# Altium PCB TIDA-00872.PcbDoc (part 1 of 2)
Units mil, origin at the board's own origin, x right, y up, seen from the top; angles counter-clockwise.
Board outline 2300 x 2250 mil, 2 copper layers (Top Layer, Bottom Layer), stack 64.8 mil thick; 81 components, 62 nets, 253 pads, 305 vias.
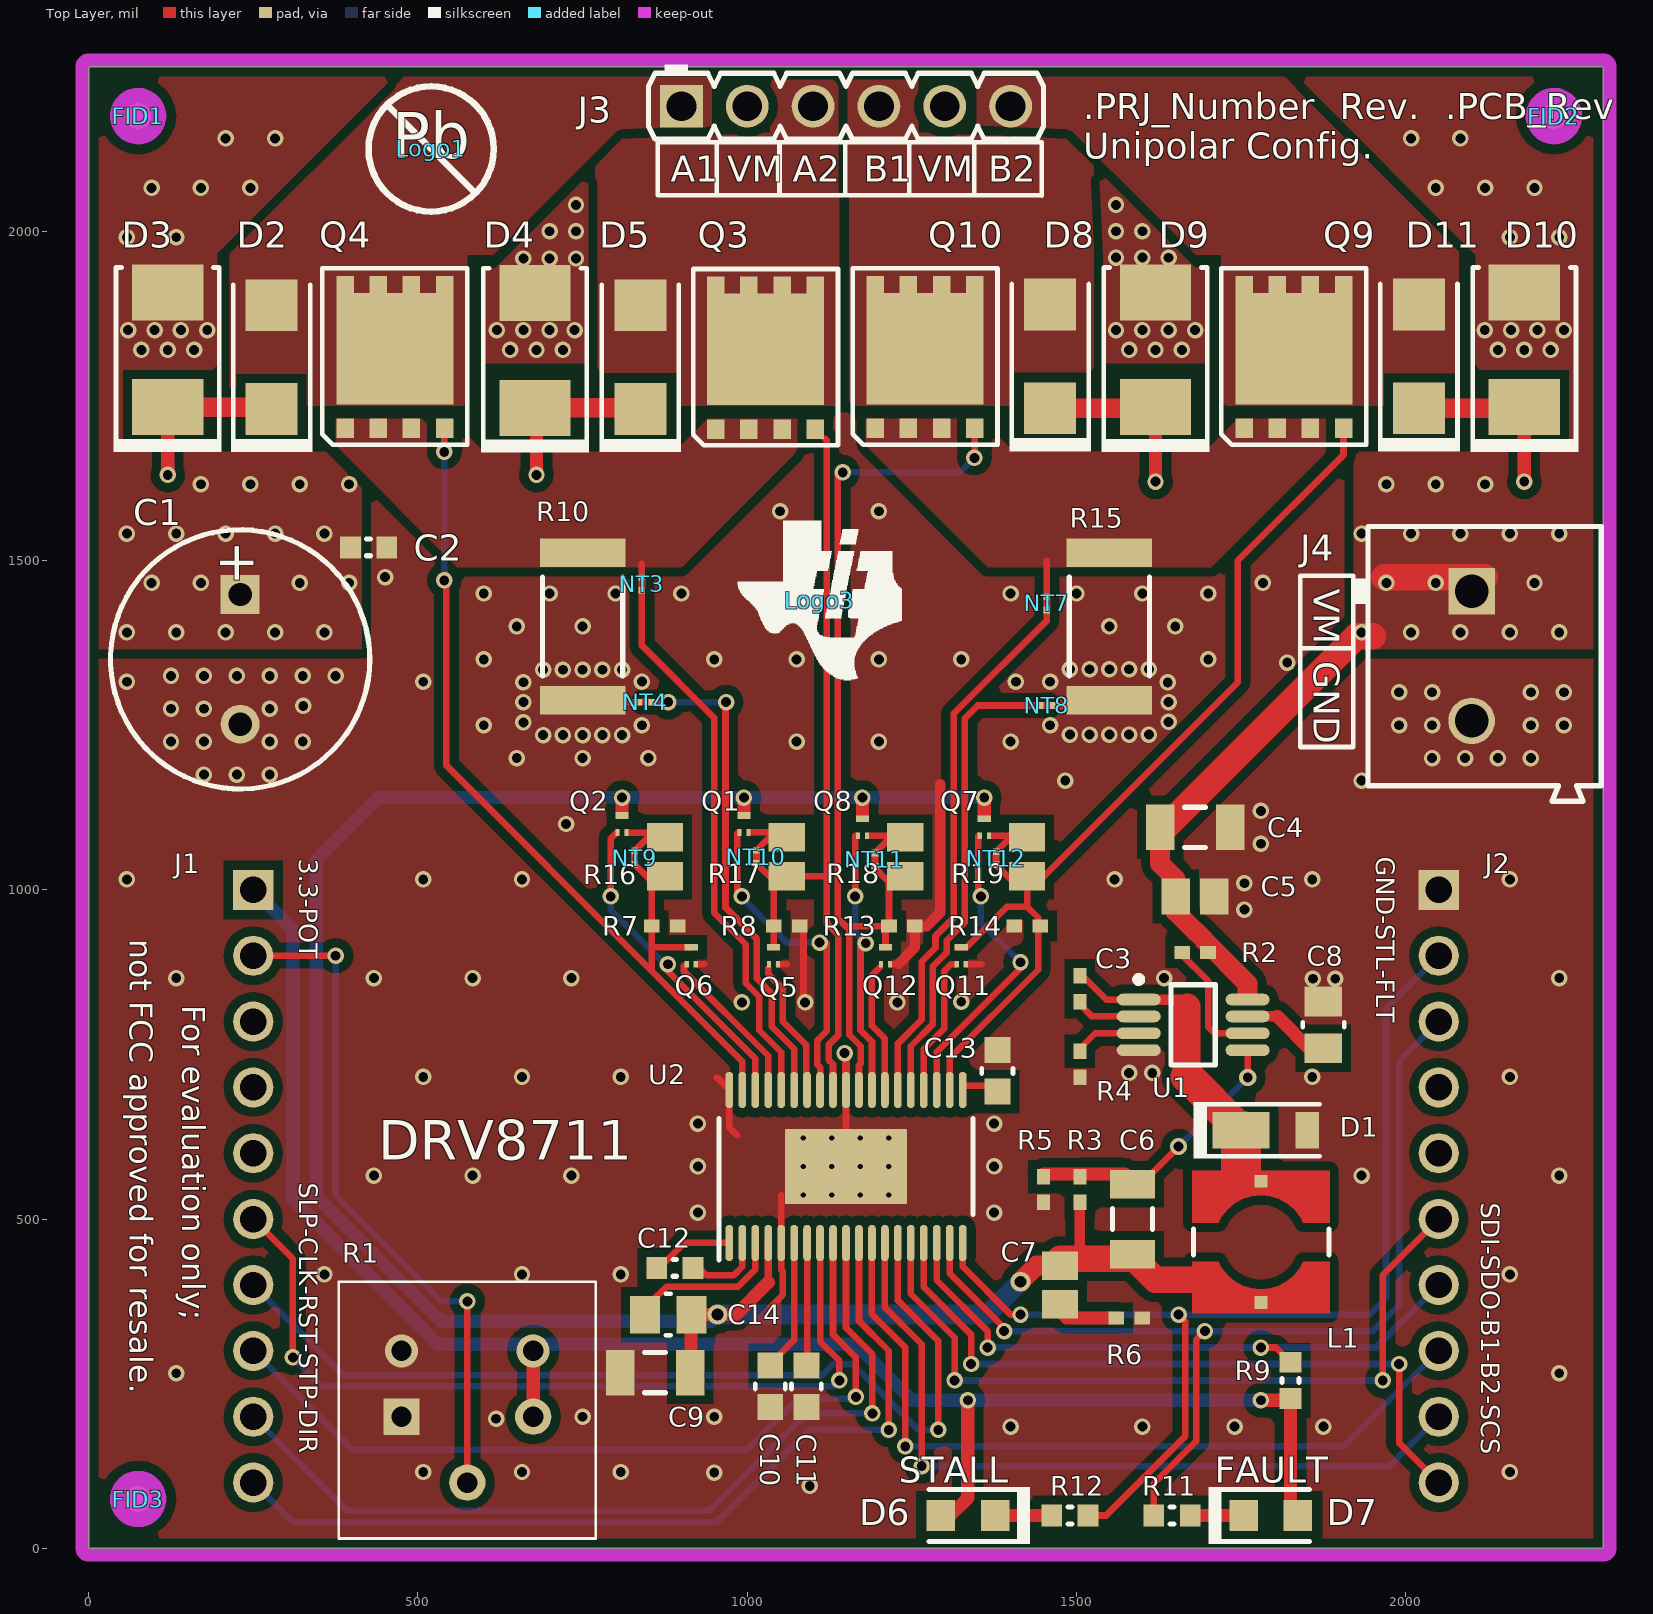
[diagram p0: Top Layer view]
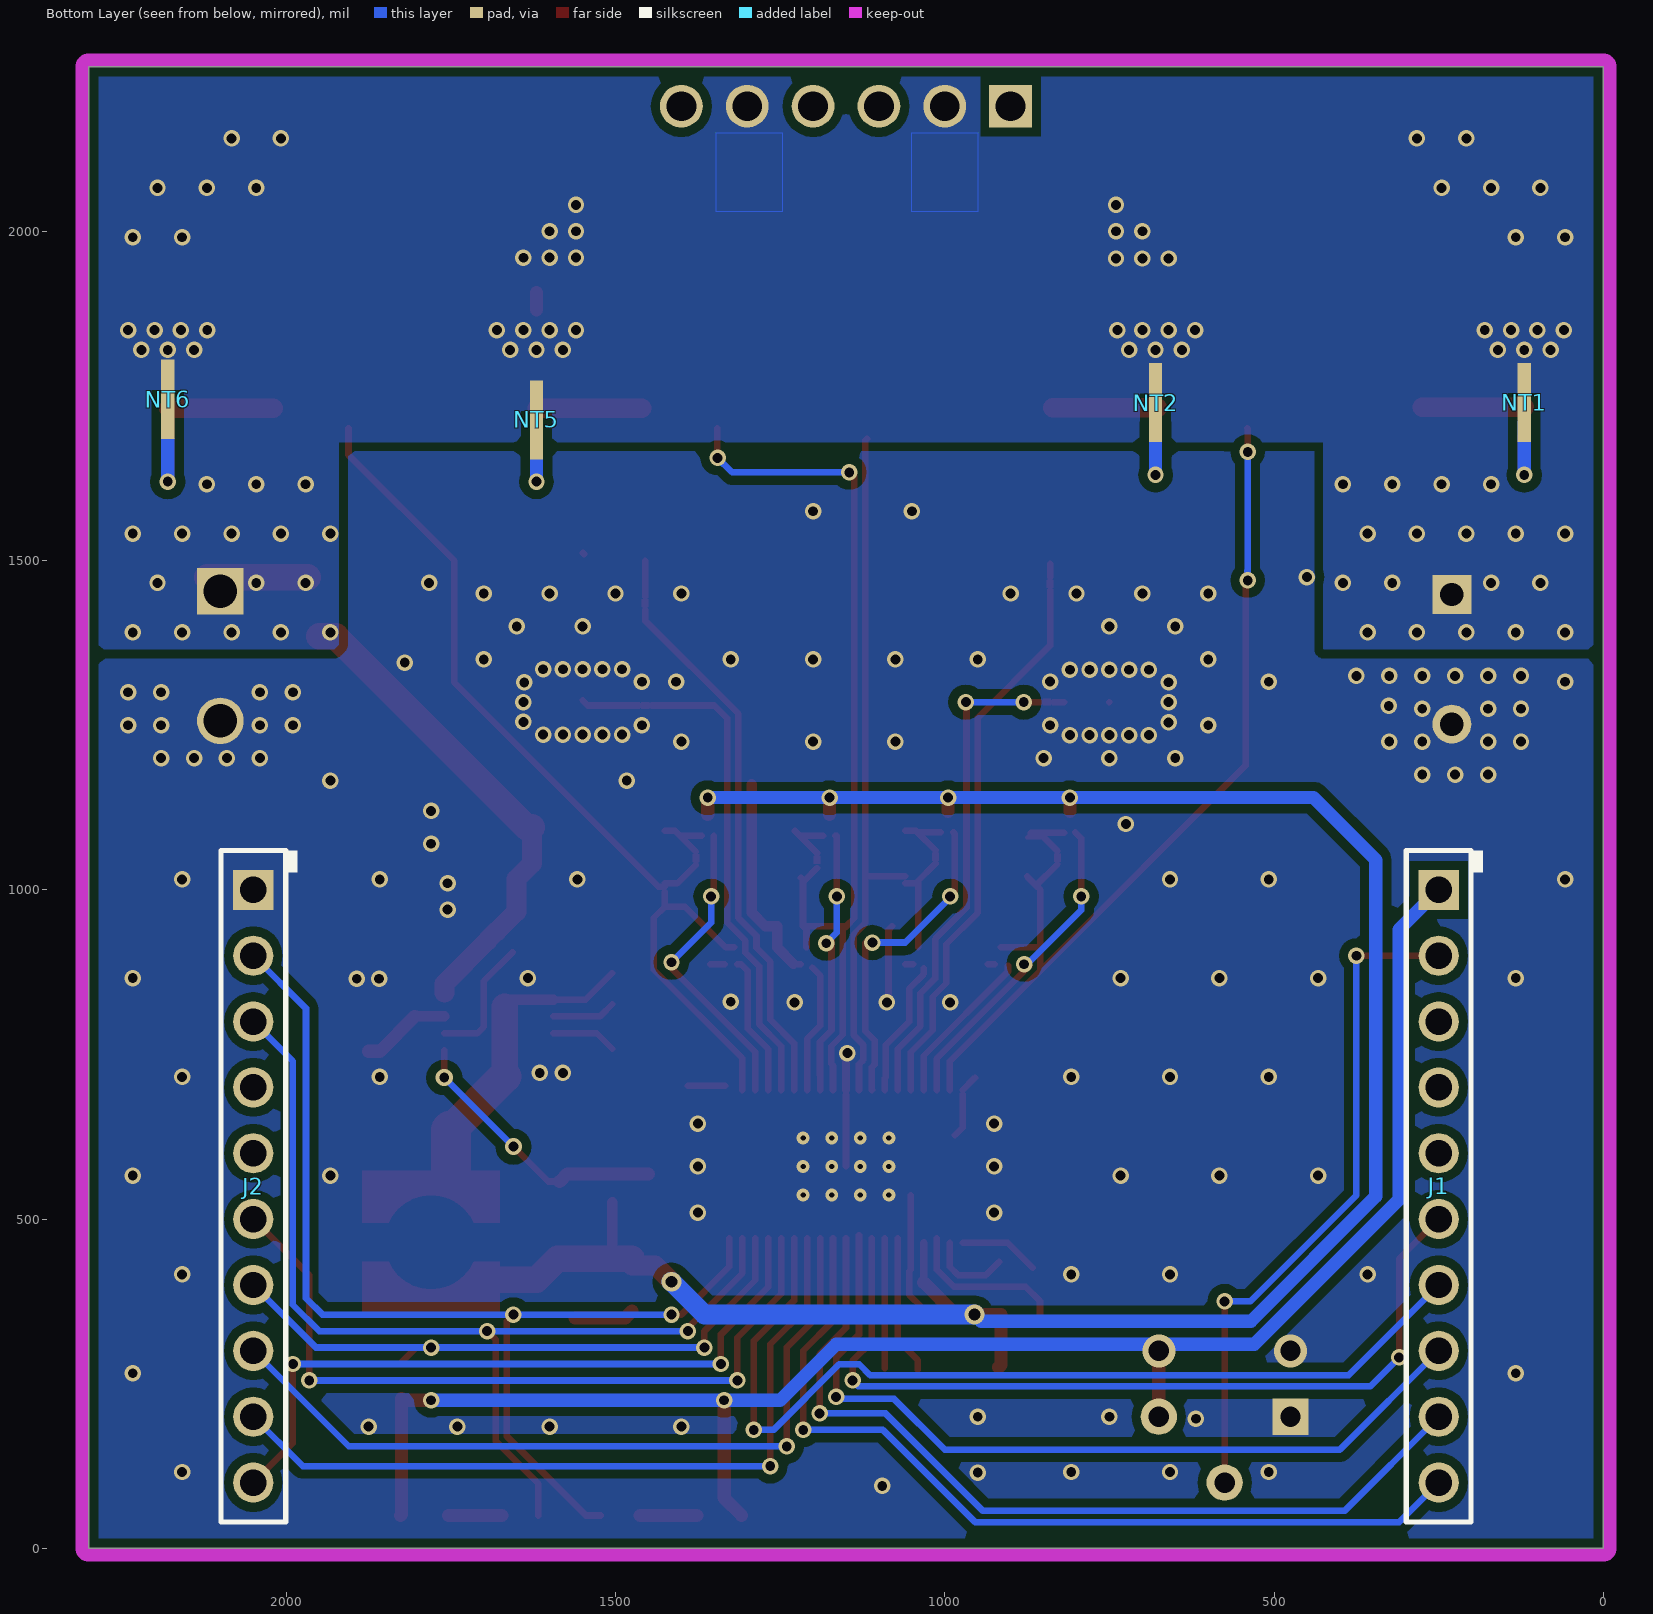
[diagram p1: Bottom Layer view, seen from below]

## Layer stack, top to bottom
Top Solder: solder mask 0.4, Solder Resist, Dk 3.5
Top Layer: signal copper 2.8
Dielectric1: core 59.2, FR-4, Dk 4.8
Bottom Layer: signal copper 2.8
Bottom Solder: solder mask 0.4, Solder Resist, Dk 3.5

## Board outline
0,0 0,2250 2300,2250 2300,0

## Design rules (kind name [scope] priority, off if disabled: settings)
AcuteAngle [All] p1: minimum=4.50000000000000E+0001 checktracksonly=FALSE
AssemblyTestPointUsage [All] p1: valid=2
Clearance Clearance_BoardEdge_MountingHoles [OnCopper and InComponentClass('Mounting Holes') vs IsKeepOut] p1: gap=15
Clearance Clearance_BoardEdge_Poly [OnCopper and InPoly vs IsKeepOut] p2: gap=15
Clearance Clearance_BoardEdge [OnCopper and Not InComponentClass('Logo') and not InComponentClass('FiducialMark') and not InRegion(1000,500,4000,800) and Not IsKeepout vs IsKeepOut] p3: gap=25
Clearance Clearance_Poly [InPolygon] p4: gap=14
Clearance [All] p5: gap=7
ComponentClearance ComponentClearance_Logo [InComponentClass(Logo)] p1: gap=10 collisioncheckmode=3 verticalgap=10 showdistances=FALSE
ComponentClearance ComponentClearance_ScrewToNut [(HasFootprint('NY PMS 440 0025 PH')) vs (HasFootprint('Keystone_1902C'))] p2: gap=5 collisioncheckmode=3 verticalgap=10 showdistances=FALSE
ComponentClearance ComponentClearance_MountingHoles [InComponentClass('Mounting Holes')] p3: gap=250 collisioncheckmode=3 verticalgap=100000 showdistances=FALSE
ComponentClearance ComponentClearance_SmallPassives [HasFootprint('0201*') or HasFootprint('0402*') or HasFootprint('0508') or HasFootprint('0603*') or HasFootprint('0612') or HasFootprint('0805*') or HasFootprint('0815*') or HasFootprint('0830*') or HasFootprint('1206*') or HasFootprint('1210*') or HasFootprint('1808*') or HasFootprint('1812*') or HasFootprint('1825*') or HasFootprint('2010*') or HasFootprint('2220*') or HasFootprint('2225*') or HasFootprint('2512*') or HasFootprint('2728*') or HasFootprint('3518*') vs HasFootprint('0201*') or HasFootprint('0402*') or HasFootprint('0508') or HasFootprint('0603*') or HasFootprint('0612') or HasFootprint('0805*') or HasFootprint('0815*') or HasFootprint('0830*') or HasFootprint('1206*') or HasFootprint('1210*') or HasFootprint('1808*') or HasFootprint('1812*') or HasFootprint('1825*') or HasFootprint('2010*') or HasFootprint('2220*') or HasFootprint('2225*') or HasFootprint('2512*') or HasFootprint('2728*') or HasFootprint('3518*')] p4: gap=10 collisioncheckmode=3 verticalgap=10 showdistances=FALSE
ComponentClearance ComponentClearance_THtoSMT [IsThruComponent vs IsSMTComponent] p5: gap=10 collisioncheckmode=3 verticalgap=100000 showdistances=FALSE
ComponentClearance ComponentClearance_THtoTH [IsThruComponent vs IsThruComponent] p6: gap=0 collisioncheckmode=3 verticalgap=0 showdistances=FALSE
ComponentClearance [All] p7: gap=10 collisioncheckmode=3 verticalgap=10 showdistances=FALSE
DiffPairsRouting [All] p1: maxlimit=100 minlimit=10 mostfreqgap=10 toplayer_minwidth=15 toplayer_maxwidth=15 toplayer_prefwidth=15 bottomlayer_minwidth=15 bottomlayer_maxwidth=15 bottomlayer_prefwidth=15 maxuncoupledlength=1000
FabricationTestPointUsage TestPointUsage [All] p1: valid=2 allowmultiple=FALSE
FabricationTestpoint Testpoint [All] p1: side=3 testpointundercomponent=TRUE minsize=40 maxsize=100 preferedsize=60 minholesize=0 maxholesize=40 preferedholesize=32 testpointgrid=1 allowsidetop=TRUE allowsidebottom=TRUE usegrid=TRUE gridtolerance=0.01
FanoutControl Fanout_LCC [IsLCC] p1: bgadir=Out bgaviamode=Centered fanoutstyle=Auto fanoutdirection=Alternating viagrid=1 // Fanout_LCC (Default Rule)
FanoutControl Fanout_BGA [IsBGA] p2: bgadir=Out bgaviamode=Centered fanoutstyle=Auto fanoutdirection=Alternating viagrid=1 // Fanout_BGA (Default Rule)
FanoutControl Fanout_Default [All] p4: bgadir=Out bgaviamode=Centered fanoutstyle=Auto fanoutdirection=Alternating viagrid=1 // Fanout_Default (Default Rule)
FanoutControl Fanout_Small [(CompPinCount < 5)] p5: bgadir=Out bgaviamode=Centered fanoutstyle=Auto fanoutdirection=OutThenIn viagrid=1 // Fanout_Small (Default Rule)
HoleSize [All] p1: absolutevalues=TRUE maxlimit=251 minlimit=7.8 maxpercent=80.000 minpercent=20.000
MinimumAnnularRing [All] p1: minimumring=5
MinimumSolderMaskSliver MinimumSolderMaskSliver_Logo [InComponentClass('Logo') vs InComponentClass('Logo')] p1: minsoldermaskwidth=0.7
MinimumSolderMaskSliver [All] p2: minsoldermaskwidth=0.4
PlaneClearance [All] p1: clearance=15
PlaneConnect [All] p1: planeconnectstyle=Direct reliefexpansion=10 reliefentries=4 reliefconductorwidth=10 reliefairgap=10
PolygonConnect PolygonConnect_1 [IsNamedPolygon('GND_TOP') or IsNamedPolygon('GND_BOT') vs Not (InComponent('U1') or InComponent('J2') or InComponent('J3') or InComponent('J5') or InComponent('C1') or InComponent('R1') or InComponent('R2') or IsStitchingVia or IsVia)] p1: connectstyle=Direct reliefconductorwidth=10 reliefentries=4 polygonreliefangle="90 Angle" airgapwidth=10
PolygonConnect [All] p2: connectstyle=Direct reliefconductorwidth=10 reliefentries=4 polygonreliefangle="90 Angle" airgapwidth=10
RoutingVias [All] p1: holewidth=15 width=25 viastyle="Through Hole" minholewidth=7.8 minwidth=19 maxholewidth=40 maxwidth=65
SMDToCorner [All] p1: distance=15000
SilkToSilkClearance [All] p1: silktosilkclearance=2
SilkToSolderMaskClearance SilkscreenOverComponentPads [All] p1: minsilkscreentomaskgap=1 clearancetoexposedcopper=FALSE
SolderMaskExpansion [All] p1: expansion=3
UnpouredPolygon [All] p1: allowunpoured=FALSE
Width [All] p1: maxlimit=100 minlimit=6 preferedwidth=10 checkconnectedcopper=TRUE
14 further rules are at their usual default settings.

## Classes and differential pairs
component class Header: J3
component class TIDA-00872_Unipolar: C1 C2 C3 C4 C5 C6 C7 C8 D1 FID1 FID2 FID3 J1 J2 J3 J4 L1 Logo1 Logo2 Logo3 R1 R2 R3 R4 R5 R6 U1
component class Logo: Logo3
component class TIDA-00872_Driver_UnipolarMotor: C9 C10 C11 C12 C13 C14 D2 D3 D4 D5 D6 D7 D8 D9 D10 D11 NT1 NT2 NT3 NT4 NT5 NT6 NT7 NT8 NT9 NT10 NT11 NT12 Q1 Q2 Q3 Q4 Q5 Q6 Q7 Q8 Q9 Q10 Q11 Q12 R7 R8 R9 R10 R11 R12 R13 R14 R15 R16 R17 R18 R19 U2
component class FiducialMark: FID1 FID2 FID3

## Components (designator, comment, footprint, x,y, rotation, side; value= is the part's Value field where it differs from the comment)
C1 "ECA-2AM101" CAPPR5-10X20 230,1350 r270 top
C2 "C1608X7R2A103K" 0603L 425,1520 r0 top
C3 "885012205031" 0402L 1505,850 r90 top
C4 "C3216X7R2A105M160AA" 1206L 1680,1095 r0 top
C5 "C2012X7R2A104K125AA" 0805L 1680,990 r0 top
C6 "C1206C122K5RACTU" 1206L 1585,500 r90 top
C7 "885012107013" 0805_145L 1475,400 r270 top
C8 "885012207049" 0805_140 1875,795 r90 top
C9 "HMK316B7105KL-T" 1206L 860,267 r180 top
C10 "885012206071" 0603_095 1035,246 r270 top
C11 "885012206052" 0603_095 1090,246 r270 top
C12 "GRM188R72A104KA35D" 0603L 890,426 r0 top
C13 "885012206034" 0603_095 1380,725 r90 top
C14 "885012207103" 0805_140 880,355 r0 top
D1 "DFLS1100-7" powerDI123 1800,635 r0 top
D2 "RB050L-60TE25" SMA 277.8,1808.97 r90 top
D3 "SMBJ60A-13-F" SMB 120,1820 r90 top
D4 "SMBJ60A-13-F" SMB 677.8,1818.97 r90 top
D5 "RB050L-60TE25" SMA 837.79,1808.97 r90 top
D6 "150080SS75000" WL-SMCW_RED_0805 1335,50 r180 top
D7 "150080SS75000" WL-SMCW_RED_0805 1795,50 r0 top
D8 "RB050L-60TE25" SMA 1460,1810 r90 top
D9 "SMBJ60A-13-F" SMB 1620,1820 r90 top
D10 "SMBJ60A-13-F" SMB 2180,1820 r90 top
D11 "RB050L-60TE25" SMA 2020,1810 r90 top
FID1 "Fiducial" Fiducial10-20 75,2175 r0 top
FID2 "Fiducial" Fiducial10-20 2225,2175 r0 top
FID3 "Fiducial" Fiducial10-20 75,75 r0 top
J1 "61301011821" Wurth_61301011821 250,550 r270 bottom
J2 "61301011821" Wurth_61301011821 2050,550 r270 bottom
J3 "61300611121" WURTH_61300611121 1150,2190 r0 top
J4 "691 101 710 002" Wurth_691101710002 2100,1355 r270 top
L1 "744043471" WE-TPC_4828 1780,465 r270 top
Logo1 "Pb-Free Symbol" Pb-Free_Overlay_Medium 520,2125 r0 top
Logo2 "FCC disclaimer" FCC_disclaimer_stacked -280,-170 r180 top
Logo3 "Texas Instruments" TI_Symbol_Overlay_Medium 1110,1440 r0 top
NT1 "Net-Tie" Net-Tie_20milWide_60milLong 120,1740 r90 bottom net-tie
NT2 "Net-Tie" Net-Tie_20milWide_60milLong 680,1740 r270 bottom net-tie
NT3 "Net-Tie" Net-Tie_10mil 840,1465 r90 top net-tie
NT4 "Net-Tie" Net-Tie_10mil 845,1285 r180 top net-tie
NT5 "Net-Tie" Net-Tie_20milWide_60milLong 1619.99,1713.7 r90 bottom net-tie
NT6 "Net-Tie" Net-Tie_20milWide_60milLong 2180,1745 r270 bottom net-tie
NT7 "Net-Tie" Net-Tie_10mil 1455,1435 r270 top net-tie
NT8 "Net-Tie" Net-Tie_10mil 1455,1280 r180 top net-tie
NT9 "Net-Tie" Net-Tie_10mil 829,1049 r90 top net-tie
NT10 "Net-Tie" Net-Tie_10mil 1014,1050 r90 top net-tie
NT11 "Net-Tie" Net-Tie_10mil 1194,1046 r90 top net-tie
NT12 "Net-Tie" Net-Tie_10mil 1378,1048 r90 top net-tie
Q1 "CSD17483F4T" YJC0003A 995,1100 r0 top
Q2 "CSD17483F4T" YJC0003A 810,1100 r0 top
Q3 "CSD19534Q5A" TRANS_NexFET_Q5A 1027.8,1808.97 r90 top
Q4 "CSD19534Q5A" TRANS_NexFET_Q5A 465,1810 r90 top
Q5 "CSD17483F4T" YJC0003A 1040,900 r0 top
Q6 "CSD17483F4T" YJC0003A 915,900 r0 top
Q7 "CSD17483F4T" YJC0003A 1360,1095 r0 top
Q8 "CSD17483F4T" YJC0003A 1175,1095 r0 top
Q9 "CSD19534Q5A" TRANS_NexFET_Q5A 1830,1810 r90 top
Q10 "CSD19534Q5A" TRANS_NexFET_Q5A 1270,1810 r90 top
Q11 "CSD17483F4T" YJC0003A 1325,900 r0 top
Q12 "CSD17483F4T" YJC0003A 1210,900 r0 top
R1 "3386P-1-104LF" BOURNS_3386P 575,210 r0 top
R2 "CRCW0402274KFKED" 0402L 1680,905 r180 top
R3 "ERJ-2RKF2201X" 0402L 1505,545 r270 top
R4 "CRCW0402154KFKED" 0402L 1505,735 r90 top
R5 "CRCW0402576RFKED" 0402L 1450,545 r90 top
R6 "ERJ-2BQFR68X" 0402L 1580,350 r180 top
R7 "CRCW0402100KFKED" 0402L 875,945 r180 top
R8 "CRCW0402100KFKED" 0402L 1060,945 r180 top
R9 "CRCW06033K30JNEA" 0603L 1825,255 r270 top
R10 "CRA2512-FZ-R050ELF" 2512L 750,1400 r90 top
R11 "CRCW0603330RJNEA" 0603L 1645,50 r180 top
R12 "CRCW0603330RJNEA" 0603L 1490,50 r180 top
R13 "CRCW0402100KFKED" 0402L 1235,945 r180 top
R14 "CRCW0402100KFKED" 0402L 1425,945 r0 top
R15 "CRA2512-FZ-R050ELF" 2512L 1550,1400 r90 top
R16 "CRCW0805100RFKEA" 0805L 875,1050 r90 top
R17 "CRCW0805100RFKEA" 0805L 1060,1050 r90 top
R18 "CRCW0805100RFKEA" 0805L 1240,1050 r90 top
R19 "CRCW0805100RFKEA" 0805L 1425,1050 r90 top
U1 "LM5009MM/NOPB" MUA08A_N 1677.17,795 r0 top
U2 "DRV8711DCPR" DCP0038A_N 1150,580 r90 top

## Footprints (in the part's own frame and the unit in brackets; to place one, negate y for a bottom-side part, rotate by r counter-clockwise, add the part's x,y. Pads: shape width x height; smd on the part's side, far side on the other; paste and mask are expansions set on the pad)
0402L [mm] "0402 from SM-752 data"
  rect 0.6x0.5 smd: 1(-0.5,0) 2(0.5,0)
  body extent -0.55,-0.3 0.55,0.3, height 0.6
0603_095 [mm] "0603_095"
  rect 1x1 smd: 1(-0.8,0) 2(0.8,0)
  silkscreen extent -0.1,-0.58 0.1,0.58, body extent -0.87,-0.48 0.87,0.48, height 0.95
0603L [mm] "0603 from SM-752 data"
  rect 0.8x0.85 smd: 1(-0.7,0) 2(0.7,0)
  silkscreen extent -0.07,-0.33 0.07,0.33, body extent -0.87,-0.47 0.87,0.47, height 0.85
0805_140 [mm] "0805 / 1.4mm height"
  rect 1.15x1.45 smd: 1(-0.9,0) 2(0.9,0)
  silkscreen extent -0.1,-0.8 0.1,0.8, body extent -1.1,-0.72 1.1,0.72, height 1.4
0805_145L [mm] "0805 / 1.45mm height"
  rect 1.1x1.4 smd: 1(-0.75,0) 2(0.75,0)
  body extent -1.1,-0.72 1.1,0.72, height 1.45
0805L [mm] "0805 from SM-752 data"
  rect 1.1x1.4 smd: 1(-0.75,0) 2(0.75,0)
  body extent -1.1,-0.72 1.1,0.72, height 1.1
1206L [mm] "1206 from SM-752 data"
  rect 1.1x1.75 smd: 1(-1.35,0) 2(1.35,0)
  silkscreen extent -0.4,-0.77 0.4,0.77, body extent -1.7,-0.9 1.7,0.9, height 1.35
2512L [mm] "Chip Resistor, Body 6.3x3.2mm, IPC High Density"
  rect 1.1x3.3 smd: 1(-2.85,0) 2(2.85,0)
  silkscreen extent -1.9,-1.55 1.9,1.55, body extent -3.22,-1.67 3.22,1.67, height 0.71
BOURNS_3386P [mil] "BOURND"
  rect 55x55 hole 31: 1(-100,-10)
  round 55 hole 31: 2(0,-110) 3(100,-10)
  silkscreen extent -195,-195 195,195, body extent -193,-192 193,193, height 201
CAPPR5-10X20 [mm] "Capacitor, Electrolytic, Radial; Body 10 x 20 mm (Dia.xH typ); Pin Spacing 5 mm (typ)"
  rect 1.5x1.5 hole 0.9: 1(-2.5,0)
  round 1.5 hole 0.9: 2(2.5,0)
  silkscreen extent -5,-5 5,5, body extent -5.01,-5.01 5.01,5.01, height 22
DCP0038A_N [mm] "TSSOP, 38-Leads, Body 9.70x4.40mm, Pitch 0.50mm, Thermal Pad 4.70x2.90mm, IPC Medium Density"
  rrect100% 1.4x0.3 smd: 1(-2.95,4.5) 2(-2.95,4) 3(-2.95,3.5) 4(-2.95,3) 5(-2.95,2.5) 6(-2.95,2) 7(-2.95,1.5) 8(-2.95,1) 9(-2.95,0.5) 10(-2.95,0) 11(-2.95,-0.5) 12(-2.95,-1) 13(-2.95,-1.5) 14(-2.95,-2) 15(-2.95,-2.5) 16(-2.95,-3) 17(-2.95,-3.5) 18(-2.95,-4) 19(-2.95,-4.5) 20(2.95,-4.5) 21(2.95,-4) 22(2.95,-3.5) 23(2.95,-3) 24(2.95,-2.5) 25(2.95,-2) 26(2.95,-1.5) 27(2.95,-1) 28(2.95,-0.5) 29(2.95,0) 30(2.95,0.5) 31(2.95,1) 32(2.95,1.5) 33(2.95,2) 34(2.95,2.5) 35(2.95,3) 36(2.95,3.5) 37(2.95,4) 38(2.95,4.5)
  rrect3% 2.9x4.7 smd: 39(0,0)
  silkscreen extent -3.6,-4.9 1.85,4.9, body extent -2.25,-4.9 2.25,4.9, height 1.22
FCC_disclaimer_stacked [mil]
Fiducial10-20 [mm]
  round 1 smd mask+0.5: 1(0,0)
  Top Layer keep-out circle w1.178: c0,0 r0.5
MUA08A_N [mm] "TSOP, 8-Leads, Body 3x3mm, Pitch 0.65mm, IPC Medium Density"
  oval 1.7x0.45 smd: 1(-2.1,0.975) 2(-2.1,0.325) 3(-2.1,-0.325) 4(-2.1,-0.975) 5(2.1,-0.975) 6(2.1,-0.325) 7(2.1,0.325) 8(2.1,0.975)
  silkscreen extent -2.22,-1.55 0.85,1.87, body extent -1.6,-1.6 1.6,1.6, height 1.09
Net-Tie_10mil [mil] "10mil net tie, no solder mask opening, no solder paste"
  rect 10x10 smd paste-5 mask-5: 1(-10,0) 2(10,0)
  Top Layer region: -6,5 6,5 6,-5 -6,-5
Net-Tie_20milWide_60milLong [mil] "20mil net tie, no solder mask opening, no solder paste"
  rect 60x20 smd paste-10 mask-10: 1(-30,0) 2(30,0)
Pb-Free_Overlay_Medium [mil]
  silkscreen extent -95,-95 95,95
powerDI123 [mm] "Diodes Inc recommended land pattern, document number DS30628 Rev. 6-2"
  rect 2.2x1.4 smd: 1(-1.275,0)
  rect 0.9x1.4 smd: 2(1.275,0)
  silkscreen extent -3.1,-1.09 1.76,1.09, body extent -2.38,-0.97 1.52,0.96, height 1
SMA [mm] "Molded Diode, 2-Leads, Body 4.3x2.6mm, IPC Medium Density, based on OnSemi component dimensions and land pattern"
  rect 2x2 smd: 1(-2,0) 2(2,0)
  silkscreen extent -3.66,-1.57 2.79,1.57, body extent -2.6,-1.3 2.6,1.3, height 2.42
SMB [mil] "Molded Diode, 2-Leads, Body 5.4x3.6mm, IPC Medium Density, based on OnSemi component dimensions"
  rect 85x107.99 smd: 1(-87.01,0) 2(87.01,0)
  silkscreen extent -155,-82 125,82, body extent -106,-71 106,71, height 91
TI_Symbol_Overlay_Medium [mil]
  silkscreen extent -124,-122 124,120
TRANS_NexFET_Q5A [mm] "TI recommended land pattern (nominal) M0139-01"
  rect 0.75x0.675 smd paste-0.1 mask+0.051: 1(-2.776,1.917) 2(-2.776,0.639) 3(-2.776,-0.639) 4(-2.776,-1.917)
  rect 0.655x0.675 smd paste-0.1 mask+0.051: 5(2.776,-1.917) 6(2.776,-0.639) 7(2.776,0.639) 8(2.776,1.917)
  rect 4.295x4.51 smd paste-2.2 mask+0.051: 9(0.301,0)
  silkscreen extent -3.4,-2.8 3.4,2.8, body extent -3.05,-2.5 3.05,2.5, height 1.11
WE-TPC_4828 [mm] "Wurth Elektronik recommended land pattern"
  rect 0.5x0.5 smd: 1(-2.35,0) 2(2.325,0)
  Top Layer region: -0.75,1.64 -1.005,1.504 -1.279,1.279 -1.504,1.005 -1.671,0.692 -1.774,0.353 -1.809,0 -1.774,-0.353 -1.671,-0.692 -1.504,-1.005 -1.279,-1.279 -1.005,-1.504 -0.75,-1.64 -0.75,-2.65 -2.75,-2.65 -2.75,2.65 -0.75,2.65
  Top Layer region: 0.75,1.64 1.005,1.504 1.279,1.279 1.504,1.005 1.671,0.692 1.774,0.353 1.809,0 1.774,-0.353 1.671,-0.692 1.504,-1.005 1.279,-1.279 1.005,-1.504 0.75,-1.64 0.75,-2.65 2.75,-2.65 2.75,2.65 0.75,2.65
  silkscreen extent -0.5,-2.6 0.5,2.63, body extent -2.51,-2.51 2.51,2.51, height 2
WL-SMCW_RED_0805 [mm] "SMD, 2-Leads, Body 1.6x0.8mm"
  rect 1.1x1.2 smd: 1(-1.05,0) 2(1.05,0)
  silkscreen extent -2.4,-1.1 1.5,1.1, body extent -1,-0.62 1,0.63, height 0.7
WURTH_61300611121 [mm] "Header, 2.54mm, 6x1, TH"
  rect 1.65x1.65 hole 1.15: 1(-6.35,0)
  round 1.65 hole 1.15: 2(-3.81,0) 3(-1.27,0) 4(1.27,0) 5(3.81,0) 6(6.35,0)
  silkscreen extent -7.62,-1.27 7.62,1.6, body extent -7.62,-1.27 7.62,1.27, height 8.54
Wurth_61301011821 [mm] "Receptacle, 2.54mm, 10x1, TH"
  rect 1.55x1.55 hole 1.02: 1(-11.43,0)
  round 1.55 hole 1.02: 2(-8.89,0) 3(-6.35,0) 4(-3.81,0) 5(-1.27,0) 6(1.27,0) 7(3.81,0) 8(6.35,0) 9(8.89,0) 10(11.43,0)
  silkscreen extent -12.95,-1.25 12.95,1.7, body extent -12.95,-1.25 12.95,1.25, height 8.5
Wurth_691101710002 [mm] "Terminal Block, 5 mm, 2x1, TH"
  rect 1.8x1.8 hole 1.3: 1(-2.5,0)
  round 1.8 hole 1.3: 2(2.5,0)
  silkscreen extent -5,-4.5 5.6,5, body extent -5.6,-4 5.6,5, height 12.5
YJC0003A [mm] "TI"
  rect 0.16x0.26 smd: 1(-0.175,-0.325) 2(0.175,-0.325)
  rect 0.51x0.26 smd: 3(0,0.325)
  body extent -0.32,-0.52 0.32,0.52, height 0.35

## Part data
C1: library part EEV-FK2A101M, "CAP ALUM 100UF 100V 20% RADIAL"
C2: "CAP, CERM, 0.01uF, 100V, +/-10%, X7R, 0603"
C3: "CAP, CERM, 0.01 µF, 16 V, +/- 10%, X7R, 0402"
C4: "CAP, CERM, 1 µF, 100 V, +/- 20%, X7R, 1206"
C5: "CAP, CERM, 0.1 µF, 100 V, +/- 10%, X7R, 0805"
C6: "CAP, CERM, 1200 pF, 50 V, +/- 10%, X7R, 1206"
C7: "CAP, CERM, 4.7 µF, 16 V, +/- 20%, X5R, 0805"
C8: "CAP, CERM, 0.47 µF, 16 V, +/- 10%, X7R, 0805_140"
C9: library part GRM31CR72A105KA01L, "CAP CER 1UF 100V 10% X7R 1206"
C10: "CAP, CERM, 0.1 µF, 25 V, +/- 10%, X7R, 0603"
C11: "CAP, CERM, 1 µF, 16 V, +/- 10%, X7R, 0603"
C12: "CAP, CERM, 0.1uF, 100V, +/-10%, X7R, 0603"
C13: "CAP, CERM, 1000 pF, 16 V, +/- 10%, X7R, 0603"
C14: "CAP, CERM, 1 µF, 50 V, +/- 10%, X7R, 0805_140"
D1: "Diode, Schottky, 100 V, 1 A, PowerDI123"
D2 D5 D8 D11: "Diode, Schottky, 60 V, 3 A, SMA"
D3 D4 D9 D10: "Diode, TVS, Uni, 60 V, 600 W, SMB"
D6 D7: "LED, Red, SMD"
FID1 FID2 FID3: "Fiducial mark.  There is nothing to buy or mount."
J1 J2: "Receptacle, 2.54mm, 10x1, Gold, TH"
J3: "Header, 2.54 mm, 6x1, Gold, TH"
J4: "Terminal Block, 5 mm, 2x1, Tin, TH"
L1: "Inductor, Shielded Drum Core, Metal Composite, 470 µH, 0.125 A, 2.128 ohm, SMD"
Logo1: library part Pb-Free
Logo2: library part FCC_disclaimer, "FCC_disclaimer"
Logo3: library part TI_Logo, "Texas Instrument Corporate Signature"
NT1 NT2 NT3 NT4 NT5 NT6 NT7 NT8 NT9 NT10 NT11 NT12: "Single point connection between nets."
Q1 Q2 Q5 Q6 Q7 Q8 Q11 Q12: "MOSFET, N/P-CH, 30 V, 1.5 A, 1.0x0.35x0.6mm"
Q3 Q4 Q9 Q10: "MOSFET, N-CH, 100 V, 10 A, SON 5x6mm"
R1: "TRIMMER, 100k ohm, 0.5W, TH"
R2: "RES, 274 k, 1%, 0.063 W, 0402"
R3: "RES, 2.20 k, 1%, 0.1 W, 0402"
R4: "RES, 154 k, 1%, 0.063 W, 0402"
R5: "RES, 576, 1%, 0.063 W, 0402"
R6: "RES, 0.68, 1%, 0.125 W, 0402"
R7 R8 R13 R14: "RES, 100 k, 1%, 0.063 W, 0402"
R9: "RES, 3.3k ohm, 5%, 0.1W, 0603"
R10 R15: "RES, 0.05 ohm, 1%, 3W, 2512"
R11 R12: "RES, 330 ohm, 5%, 0.1W, 0603"
R16 R17 R18 R19: "RES, 100, 1%, 0.125 W, 0805"
U1: "150 mA, 100V Step-Down Switching Regulator, 8-pin MSOP, Pb-Free"
U2: "STEPPER MOTOR CONTROLLER IC, DCP0038A"

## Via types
v1: diameter 25, hole 15, Top Layer to Bottom Layer, tented both sides, 286 vias
v2: diameter 19.68, hole 7.87, Top Layer to Bottom Layer, tented both sides, 12 vias
v3: diameter 50, hole 31, Top Layer to Bottom Layer, tented both sides, 2 vias
v4: diameter 26, hole 15, Top Layer to Bottom Layer, tented both sides, 2 vias
v5: diameter 30, hole 18, Top Layer to Bottom Layer, tented both sides, 2 vias
v6: diameter 25, hole 15, Top Layer to Bottom Layer, 1 vias

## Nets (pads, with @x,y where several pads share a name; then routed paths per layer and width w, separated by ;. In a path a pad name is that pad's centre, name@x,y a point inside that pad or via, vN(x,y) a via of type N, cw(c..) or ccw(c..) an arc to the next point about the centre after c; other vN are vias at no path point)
3.3V: D6.2 D7.2 J1.1 R1.3 R9.2 | length 2611.1
  Top Layer w20: R1.3@675,200 v3@675,310 ; D6.2@1308.66,50 1335,76.34 v1(1335,225) ; v1(1780,225) 1822.56,225 R9.2@1825,227.44 1825,51.34 D7.2@1826.34,50
  Bottom Layer w20: J1.1@250,1000 310,940 310,530 530,310 1165,310 1250,225 v1(1335,225) v1(1780,225)
  other v3: 675,300
A1HS: Q2.1 U2.36 | length 497.1
  Top Layer w10: v1(792.82,990) 793,990.18 793,1078.46 Q2.1@801.74,1087.2 ; v1(879.5,887.06) 875.11,887.06 872,883.96 1012.2,743.75 U2.36@1012.2,696.14
  Bottom Layer w10: v1(792.82,990) 792.82,969.18 874.94,887.06 v1(879.5,887.06)
A1LS: Q6.1 U2.35 | length 241.8
  Top Layer w10: 904,885 904,876 1031.89,748.11 U2.35@1031.89,696.14
A2HS: Q1.1 U2.31 | length 493
  Top Layer w10: Q1.1@986.74,1087.2 985,1085.46 985,995 990,990 v1(992,990) ; U2.31@1110,696.77 U2.31@1110.63,696.14 1110.63,730.68 1106.5,734.81 1106.5,771.5 1121,786 1121,919 1120,920 v1(1110,920)
  Bottom Layer w10: v1(992,990) 992,988 1060,920 v1(1110,920)
A2LS: Q5.1 U2.32 | length 209
  Top Layer w10: 1031.74,880.59 1031.74,872.3 1054,850.04 1054,800 1089.5,764.5 1089.5,715.5 1090.94,714.06 U2.32@1090.94,696.14
AISENN: NT4.1 U2.33 | length 745.5
  Top Layer w10: NT4.1@855,1285 v6(880,1285) ; v1(968,1285) 967,1284 967,973 1014.74,925.26 1014.74,865.26 1037,843 1037,792.96 1071.26,758.7 U2.33@1071.26,696.14
  Bottom Layer w10: v6(880,1285) v1(968,1285)
AISENP: NT3.1 U2.34 | length 846.5
  Top Layer w10: NT3.1@840,1455 840,1371 950,1261 950,965 997.74,917.26 997.74,858.22 1018.34,837.62 1018.34,786.66 1051.57,753.43 U2.34@1051.57,696.14
AOUT1: NT9.1 Q4.4 Q6.3 R7.2 R16.1 U2.37 | length 1463.9
  Top Layer w10: v1(540,1470) 540,1475 543.29,1478.29 543.29,1188.63 855,876.92 ; v1(540,1665) 540,1700.2 Q4.4@540.49,1700.7 ; NT9.1@829,1039 R16.1@861.26,1006.74 ; 857.8,912.8 Q6.3@915,912.8 ; R16.1@875,1020.47 R16.1@861.26,1006.74 ; U2.37@992.52,696.14 992.52,739.4 855,876.92 ; 855,876.92 855,1000.47 R16.1@861.26,1006.74
  Bottom Layer w10: v1(540,1470) 540,1484.02 540.49,1484.51 540,1485 v1(540,1665)
AOUT2: NT10.1 Q3.4 Q5.3 R8.2 R17.1 U2.30 | length 1224.9
  Top Layer w10: NT10.1@1014,1040 R17.1@1044,1010 ; Q5.3@1040,912.8 1040.31,913.11 R8.2@1040.31,945 1040.31,1010 R17.1@1060,1010 ; R17.1@1060,1020.47 1119.03,1020.47 ; 1117.64,1685.32 1120.5,1682.45 1120.5,949.85 1132,938.35 1132,938 1138,932 1138,778.96 1123.5,764.46 1123.5,741.85 1130.31,735.04 U2.30@1130.31,696.14
B1HS: Q8.1 U2.27 | length 507.5
  Top Layer w10: 1163.89,1082 v1(1163.9,990) 1164,990.1 1164,1082 Q8.1@1166,1082 ; v1(1180,919) 1176.04,922.96 1172,922.96 1172,786.96 1189.5,769.46 1189.5,718.46 1189.37,718.33 U2.27@1189.37,696.14
  Bottom Layer w10: v1(1163.9,990) 1163.9,935.1 v1(1180,919)
B1LS: Q12.1 U2.26 | length 199.2
  Top Layer w10: 1201.19,882 1189,869.81 1189,794 1209.06,773.94 U2.26@1209.06,696.14
B2HS: Q7.1 U2.22 | length 469.8
  Top Layer w10: U2.22@1287.8,696.14 1287.8,753.8 1420,886 1416,890 v1(1415,890) ; Q7.1@1351.11,1082.2 1351.11,994.5 1351.74,993.13 v1(1354.87,990)
  Bottom Layer w10: v1(1354.87,990) 1354.87,950.13 v1(1415,890)
B2LS: Q11.1 U2.23 | length 213.7
  Top Layer w10: U2.23@1268.11,696.14 1268.11,758.15 1299,789.04 1299,876.4 1309.8,887.2 Q11.1@1315.16,887.2
BEMF: C13.1 U2.20 | length 56.8
  Top Layer w10: 1333.46,702.44 C13.1@1390.27,702.44
BIN1: J2.8 U2.12 | length 1206.8
  Top Layer w10: U2.12@1189.37,470.75 1189.37,355.63 1240,305 v1(1240,155)
  Bottom Layer w10: v1(1240,155) 1905,155 J2.8@2050,300
BIN2: J2.9 U2.13 | length 1185
  Top Layer w10: U2.13@1209.06,470.75 1209.06,365.94 1265,310 v1(1265,125)
  Bottom Layer w10: v1(1265,125) 1975,125 J2.9@2050,200
BISENN: NT8.2 U2.24 | length 720.9
  Top Layer w10: U2.24@1248.43,696.14 1248.43,762.51 1282,796.08 1282,883.96 1299.35,901.31 1302.96,904.92 1302.96,922.88 1330.37,950.29 1330.37,1260.37 1350,1280 NT8.2@1445,1280
BISENP: NT7.2 U2.25 | length 822.6
  Top Layer w10: U2.25@1228.74,696.14 1228.74,766.86 1265,803.12 1265,891 1285.96,911.96 1285.96,929.93 1313.37,957.33 1313.37,1267.41 1455,1409.04 NT7.2@1455,1425
BOUT1: NT11.1 Q10.4 Q12.3 R13.2 R18.1 U2.28 | length 1418.3
  Top Layer w10: v1(1145,1634) 1142,1634 1137.5,1629.5 1137.5,956.89 1149.39,945 ; U2.28@1169.68,696.14 1169.68,733.23 1172.5,736.04 1172.5,762.42 1155,779.92 1155,939.39 1149.39,945 ; NT11.1@1194,1033 R18.1@1213.5,1013.5 ; Q12.3@1210,912.8 1210,939.69 R13.2@1215.31,945 ; R18.1@1218.66,1018.66 1215.31,1015.31 R13.2@1215.31,945 ; v1(1345,1656) 1345.49,1656.49 Q10.4@1345.49,1700.7 ; 1149.39,945 R13.2@1215.31,945
  Bottom Layer w10: v1@1142,1634 v1(1145,1634) 1323,1634 v1(1345,1656)
BOUT2: NT12.1 Q9.4 Q11.3 R14.2 R19.1 U2.21 | length 1458.4
  Top Layer w10: U2.21@1307.48,696.14 1307.48,744.48 1441.79,878.79 1441.79,957.53 1425,974.32 ; Q11.3@1320,912.8 Q11.3@1325,912.8 1332.8,912.8 1394.32,974.32 1425,974.32 ; NT12.1@1378,1038 1406,1010 1425,1010 1425,1005 1435,1005 1745,1315 1745,1500 1905.49,1660.49 Q9.4@1905.49,1700.7 ; 1425,997.32 1425,974.32
CP1: C12.1 U2.1 | length 122.1
  Top Layer w10: C12.1@866.44,426 904.3,463.86 U2.1@972.83,463.86
CP2: C12.2 U2.2 | length 124.7
  Top Layer w10: C12.2@917.56,435 937.56,415 979.85,415 992.52,427.67 U2.2@992.52,463.86
DIR/AIN2: J1.10 U2.11 | length 1357.4
  Top Layer w10: U2.11@1169.68,470.75 1169.68,345.32 1215,300 v1(1215,180)
  Bottom Layer w10: J1.10@250,100 310,40 953.98,40 1093.98,180 v1(1215,180)
GND: C1.2 C2.2 C4.2 C5.2 C8.2 C9.2 C10.2 C11.2 C13.2 D1.2 J2.1 J4.2 NT4.2 NT8.1 Q5.2 Q6.2 Q11.2 Q12.2 R1.1 R4.1 R5.1 R6.1 R7.1 R8.1 R10.1 R13.1 R14.1 R15.1 U1.4 U2.5 U2.29 U2.38 U2.39 | length 1024.9
  Top Layer w10: R10.1@750,1284.92 R10.1@750.08,1285 ; 818.96,1285 NT4.2@835,1285 ; Q6.2@924.32,887 935,887 ; 954,714.98 U2.38@972.83,696.14 ; U2.38@972.83,689.25 972.83,639.06 984.65,627.24 ; 1035,366.11 1053.89,385 1053.89,421 1051.57,423.32 U2.5@1051.57,463.86 1051.57,536.43 ; Q5.2@1048.29,887.2 1060.2,887.2 ; R8.1@1079.68,945 1085.5,939.18 v1@1085.5,831.5 ; v1(1148,752) v1@1150,750 ; U2.39@1150,580 U2.29@1150,689.25 ; Q12.2@1219,887 1231.49,887 ; Q11.2@1334,887 1355.91,887 ; NT8.1@1465,1280 1542.2,1280 R15.1@1550,1287.8
  Top Layer w12: U2.29@1150,696.14 v1@1150,750
  Top Layer w16: 1230,887.82 1254.68,912.51 R13.1@1254.68,945 1272.75,945 1293.37,965.62 1293.37,1160
  other v1: 1095,95 950,115 508,116 658,116 808,116 2158,116 1400,185 1600,185 1740,185 1875,185 618.69,196.95 750,200 950,200 133,266 2233,266 358,416 658,416 808,416 2158,416 925,510 1375,510 433,566 583,566 733,566 1933,566 2233,566 925,580 1375,580 925,645 1375,645 508,716 658,716 808,716 1858,716 2158,716 1580,722.17 1615,722.17 992,829 1088,829 1228,829 1325,830 1859,865 1893,865 133,866 433,866 583,866 733,866 1633,866 2233,866 1755,970 1755,1010 58,1016 508,1016 658,1016 1558,1016 1858,1016 2158,1016 1780,1070 725,1100 1780,1120 1483,1166 1933,1166 175,1175 225,1175 275,1175 650,1200 750,1200 850,1200 2040,1200 2090,1200 2140,1200 2190,1200 125,1225 175,1225 275,1225 325,1225 1075,1225 1200,1225 1400,1225 690,1235 720,1235 750,1235 780,1235 810,1235 1490,1235.71 1520,1235.71 1550,1235.71 1580,1235.71 1610,1235.71 600,1250 840,1250 1460,1250 1990,1250 2040,1250 2190,1250 2240,1250 660,1254.32 1640,1255 125,1275 175,1275 275,1275 325.86,1279.35 660,1285 1640,1285 1990,1300 2040,1300 2190,1300 2240,1300 660,1315.32 1638.58,1315 58,1316 508,1316 840,1316.32 1408,1316 1460,1316 125,1325 175,1325 225,1325 275,1325 325,1325 375,1325 690,1334.29 720,1334.29 750,1334.29 780,1334.29 810,1334.29 1490,1335 1520,1335 1550,1335 1580,1335 1610,1335 1820,1345 600,1350 950,1350 1075,1350 1200,1350 1325,1350 1700,1350 650,1400 750,1400 1550,1400 1650,1400 600,1450 700,1450 800,1450 900,1450 1400,1450 1500,1450 1600,1450 1700,1450 1783,1466 450,1475 1050,1575 1200,1575
  other v2: 1085.04,536.69 1128.35,536.69 1171.65,536.69 1214.96,536.69 1085.04,580 1128.35,580 1171.65,580 1214.96,580 1085.04,623.31 1128.35,623.31 1171.65,623.31 1214.96,623.31
  other v3: 475,300
GND_A: NT3.2 Q3.1 Q3.2 Q3.3 Q4.1 Q4.2 Q4.3 R10.2 | length 20
  Top Layer w10: NT3.2@840,1475 840,1495
GND_B: NT7.1 Q9.1 Q9.2 Q9.3 Q10.1 Q10.2 Q10.3 R15.2 | length 58.1
  Top Layer w10: NT7.1@1455,1445 1455,1500 ; R15.2@1547.8,1510 R15.2@1550,1512.2
MTR_A1: D2.2 J3.1 Q4.5 Q4.6 Q4.7 Q4.8 Q4.9
MTR_A2: D5.2 J3.3 Q3.5 Q3.6 Q3.7 Q3.8 Q3.9
MTR_B1: D8.2 J3.4 Q10.5 Q10.6 Q10.7 Q10.8 Q10.9
MTR_B2: D11.2 J3.6 Q9.5 Q9.6 Q9.7 Q9.8 Q9.9
NetC3_1: C3.1 U1.2 | length 97.2
  Top Layer w10: C3.1@1505,826.38 1523.58,807.8 U1.2@1594.49,807.8
NetC3_2: C3.2 D1.1 L1.1 U1.1 | length 472.6
  Top Layer w10: C3.2@1505,873.62 1545.24,833.39 U1.1@1594.49,833.39
  Top Layer w16: U1.1@1594.49,833.39 1657.17,833.39 1668,822.56
  Top Layer w40: 1668,716.8 1668,822.56
  Top Layer w50: 1668,716.8 D1.1@1749.8,635
  Top Layer w60: 1749.8,568.03 D1.1@1749.8,635
NetC6_2: C6.2 R3.1 R5.2 U1.5 | length 421.9
  Top Layer w10: C6.2@1585,557.09 1602.09,557.09 v4(1655,610) ; U1.5@1759.84,756.61 1759.84,715.16 v4(1760,715)
  Top Layer w20: R5.2@1450,568.62 1505,568.62 1573.46,568.62 C6.2@1585,557.09
  Bottom Layer w10: v4(1655,610) v4(1760,715)
NetC7_2: C7.2 R6.2 | length 90.5
  Top Layer w20: C7.2@1475,360 1485,350 R6.2@1561.38,350
NetC8_1: C8.1 U1.7 | length 137
  Top Layer w16: U1.7@1759.84,807.8 1804.8,807.8
  Top Layer w20: 1804.8,807.8 1857.59,755 C8.1@1875,755
NetD2_1: D2.1 D3.1 NT1.1 | length 297.9
  Top Layer w20: v1(120,1630) 120,1688.99 ; D2.1@275.03,1732.99 D2.1@277.8,1730.23
  Top Layer w30: D3.1@120,1732.99 D2.1@275.03,1732.99
  Bottom Layer w20: v1(120,1630) NT1.1@120,1710
NetD4_1: D4.1 D5.1 NT2.2 | length 343.6
  Top Layer w20: D4.1@677.8,1731.96 680,1729.76 v1(680,1630) ; D5.1@836.06,1731.96 D5.1@837.79,1730.23
  Top Layer w30: D4.1@677.8,1731.96 D5.1@836.06,1731.96
  Bottom Layer w20: v1(680,1630) NT2.2@680,1710
NetD6_1: D6.1 R12.2 | length 86.1
  Top Layer w20: D6.1@1376.34,50 R12.2@1462.44,50
NetD7_1: D7.1 R11.1 | length 81.1
  Top Layer w20: R11.1@1672.56,50 D7.1@1753.66,50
